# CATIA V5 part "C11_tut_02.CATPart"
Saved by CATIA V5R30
Part number: Part2
Material "Grey Blue": density 7860 kg/m3, Young's modulus 2e+11 Pa, Poisson ratio 0.266
Bounding box of the stored display mesh (mm): x 0 to 175, y -36.636 to 105, z 0 to 36.66
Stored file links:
  D:\PROJECTS\Resources\c11\C11tut2.CATPart
  C:\Program Files\Dassault Systemes\B30\win_b64\startup\materials\brushed_metal2.jpg
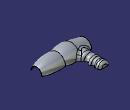
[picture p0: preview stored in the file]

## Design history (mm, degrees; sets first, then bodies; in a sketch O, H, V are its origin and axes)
Body1 (main body), material "Grey Blue"
  Plane1: type Offset, RefPlane yz-plane, Offset 50
  Set1
    Plane2: type Offset, RefPlane yz-plane, Offset 100 {= Plane1.Offset+`Plane2.Relative Offset`}
    Plane3: type Offset, RefPlane yz-plane, Offset 175
  Sketch1 on yz-plane, origin (0, 0, 0), H (0, 1, 0), V (0, 0, 1)
    arc A1 centre (0, 0) radius 25 from (25, 0) to (-25, 0) ccw
    point P1 (-25, 0)
    radius A1 = 25
  Sketch2 on Plane1, origin (50, 0, 0), H (0, 1, 0), V (0, 0, 1)
    arc A1 centre (0, 0) radius 35 from (35, 0) to (-35, 0) ccw
    point P1 (-35, 0)
    radius A1 = 35
  Sketch3 on Plane2, origin (100, 0, 0), H (0, 1, 0), V (0, 0, 1)
    arc A1 centre (0, 0) radius 30 from (30, 0) to (-30, 0) ccw
    point P1 (-30, 0)
    radius A1 = 30
  Sketch4 on Plane3, origin (175, 0, 0), H (0, 1, 0), V (0, 0, 1)
    arc A1 centre (0, 0) radius 20 from (20, 0) to (-20, 0) ccw
    point P1 (-20, 0)
    radius A1 = 20
  Sketch5 on xy-plane, origin (0, 0, 0), H (1, 0, 0), V (0, 1, 0)
    point P1 (0, -25)
    line L1 (0, -25) -> (50, -35)
    point P2 (50, -35)
    reference projected point E1 (50, -35) from Sketch2.P1
    reference projected point E2 (0, -25) from Sketch1.P1
    arc A1 centre (66.816, 49.3399) radius 86 from (50, -35) to (100, -30) ccw
    point P4 (100, -30)
    reference projected point E3 (100, -30) from Sketch3.P1
    arc A2 centre (121.7543, 93.0924) radius 125 from (100, -30) to (175, -20) ccw
    point P6 (175, -20)
    reference projected point E4 (175, -20) from Sketch4.P1
    radius A1 = 86
    radius A2 = 125
    coincidence: P1 V, P2 E1, P1 E2, P4 E3, E4 P6
  Sketch6 on xy-plane, origin (0, 0, 0), H (1, 0, 0), V (0, 1, 0)
    arc A1 centre (121.7543, -93.0924) radius 125 from (100, 30) to (175, 20) cw
    arc A2 centre (66.816, -49.3399) radius 86 from (50, 35) to (100, 30) cw
    line L1 (0, 25) -> (50, 35)
    fix: A1, L1, A2
  Loft1: Sections (Sketch1; Sketch2; Sketch3; Sketch4), Guides (Sketch5; Sketch6)
  Sketch7 on xy-plane, origin (0, 0, 0), H (1, 0, 0), V (0, 1, 0)
    point P1 (15, 105)
    line L1 (15, 105) -> (15, 0)
    point P2 (15, 0)
    point P3 (15, 105)
    distance H P1 = 105
    distance V L1 = 15
    coincidence: P2 H, P3 P1
    vertical: L1 V
  Plane4: type Normal, Curve Sketch7, RefPoint Sketch7.P3, Ratio 0
  Sketch8 on Plane4, origin (0, 105, 0), H (1, 0, 0), V (0, 0, 1)
    arc A1 centre (32.5, 0) radius 17.5 from (15, 0) to (50, 0) cw
    point P1 (32.5, 0)
    point P2 (15, 0)
    point P3 (50, 0)
    reference projected line E1 (0, 0) -> (-50, 0) from edge of Loft1
    reference projected point E2 (15, 0) from Sketch7.P2
    radius A1 = 17.5
    coincidence: P2 H, P3 H, P1 E1, E2 P2
  Sketch9 on xy-plane, origin (0, 0, 0), H (1, 0, 0), V (0, 1, 0)
    line L1 (50, 105) -> (51.989, 90.8478)
    point P1 (50, 105)
    arc A1 centre (45.0571, 89.8736) radius 7 from (51.989, 90.8478) to (49.6106, 84.5571) cw
    arc A2 centre (53.5135, 80) radius 6 from (49.6106, 84.5571) to (51.6373, 74.3009) ccw
    point P5 (53.5135, 80)
    point P6 (51.6373, 74.3009)
    arc A3 centre (50.1519, 69.7891) radius 4.75 from (51.6373, 74.3009) to (52.3972, 65.6033) cw
    point P8 (51.6373, 74.3009)
    arc A4 centre (56.6515, 57.6723) radius 9 from (52.3972, 65.6033) to (52.5866, 49.6425) ccw
    point P10 (56.6515, 57.6723)
    arc A5 centre (47.1667, 38.9362) radius 12 from (52.5866, 49.6425) to (59.0499, 40.6063) cw
    construction line L2 (50, 105) -> (61.1145, 25.9165)
    line L3 (59.0499, 40.6063) -> (64.9839, -1.6159)
    reference projected point E1 (50, 105) from Sketch8.P3
    axis line L4 (15, 105) -> (65.4512, 105)
    point P16 (15, 105)
    radius A1 = 7
    radius A2 = 6
    radius A3 = 4.75
    radius A4 = 9
    radius A5 = 12
    distance P5 P1 V = 25
    angle L4 L1 = 82
    distance P1 P16 = 35
    tangency: A2 A1, A3 L2, A3 A2, A3 A4, A5 A4, A5 L2, L3 A5, L3 L2, A1 L1
    coincidence: P8 A2, L2 L1, P5 L2, P8 P6, P10 L2, P1 E1
    horizontal: L4 H
  Loft2: Sections Sketch8, Guides (Sketch9; Sketch7)
  Trim1: Trimmed (Loft1; Loft2)
  Line1: type PtPt, FirstPoint vertex [face of Loft1], SecondPoint vertex [face of Loft1]
  Line2: type PtPt, FirstPoint vertex [face of Loft2], SecondPoint vertex [face of Loft2]
  Line3: type PtPt, FirstPoint vertex [face of Loft1], SecondPoint vertex [face of Loft1]
  Fill1: Boundary (Line3; edge of Loft1)
  Fill2: Boundary (edge of Loft1; Line1)
  Fill3: Boundary (edge of Loft2; Line2)
  Join1: Elements (Fill2; Fill3; Fill1; Trim1)
  CloseSurface1: CloseElement Join1
  Fillet1: radius 8, on edge [face of CloseSurface1 | face of CloseSurface1]
  Fillet2: radius 12, on edge [face of CloseSurface1 | face of CloseSurface1]
  Shell1: ExtOffset 0, Face (face of CloseSurface1; face of CloseSurface1; face of CloseSurface1), IntOffset 1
